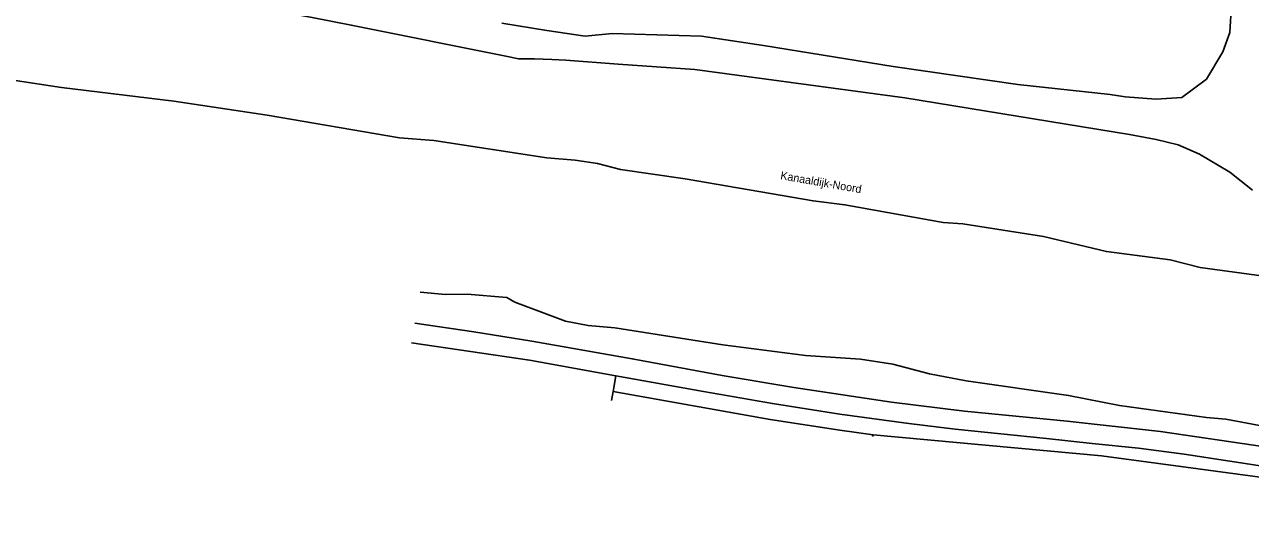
# Model space of a CAD drawing. Extents: x 164150 to 165261, y 382513 to 383432.
# Drawn here: x 165024.1 to 165177.4, y 382531.9 to 382595.7 of the extents above; entities that cross this region are included whole.
import ezdxf

# ---------------------------------------------------------------- set-up
doc = ezdxf.new("R2010")
doc.units = 0
for name, color, linetype in [('IMGEO_Berm_groen', 7, 'Continuous'), ('IMGEO_Fietspad_gesloten', 7, 'Continuous'), ('IMGEO_Hek', 7, 'Continuous'), ('IMGEO_Loofbos', 7, 'Continuous'), ('IMGEO_Openbare_ruimte_label', 7, 'Continuous'), ('IMGEO_Rijbaan_lokaal_onverhard', 7, 'Continuous'), ('IMGEO_Waterloop', 7, 'Continuous')]:
    doc.layers.add(name, color=color, linetype=linetype)

msp = doc.modelspace()

# ---------------------------------------------------------------- linework, layer by layer
at = {"layer": 'IMGEO_Berm_groen'}
for points in [[(165097.71, 382549.86), (165098.06, 382551.85)], [(165130.21, 382544.47), (165126.04, 382545.03), (165117.34, 382546.39), (165097.71, 382549.86)], [(165227.27, 382531.88), (165202.11, 382536.01), (165158.73, 382541.84), (165130.21, 382544.47)]]:
    msp.add_lwpolyline(points, dxfattribs=at)
at = {"layer": 'IMGEO_Fietspad_gesloten'}
for points in [[(165072.92, 382558.41), (165080.3, 382557.33), (165087.54, 382556.17), (165100.1, 382553.97), (165111.35, 382551.86), (165120.31, 382550.36), (165132.5, 382548.56), (165141.61, 382547.42), (165154.46, 382546.15), (165166.12, 382544.86), (165179.14, 382542.97), (165196.27, 382540.2), (165213.12, 382537.59), (165230.08, 382534.68)], [(165072.49, 382555.97), (165087.26, 382553.78), (165098.06, 382551.85)], [(165098.06, 382551.85), (165109.02, 382549.87), (165117.62, 382548.37), (165126.06, 382547.04), (165134.67, 382545.87), (165140.44, 382545.17), (165151.88, 382544), (165157.59, 382543.39), (165163.35, 382542.78), (165169.08, 382542.04), (165191.9, 382538.55), (165228.77, 382532.6)]]:
    msp.add_lwpolyline(points, dxfattribs=at)
at = {"layer": 'IMGEO_Hek'}
msp.add_lwpolyline([(165097.52, 382548.77), (165097.71, 382549.86)], dxfattribs=at)
at = {"layer": 'IMGEO_Loofbos'}
for points in [[(165097.71, 382549.86), (165097.52, 382548.77)], [(165130.21, 382544.47), (165130.13, 382544.27)]]:
    msp.add_lwpolyline(points, dxfattribs=at)
at = {"layer": 'IMGEO_Rijbaan_lokaal_onverhard'}
for points in [[(165022.71, 382602.49), (165025.2, 382602.49), (165028.36, 382602.25), (165044.09, 382599.56), (165060.08, 382596.6), (165064.98, 382595.66), (165084.72, 382591.68), (165085.9, 382591.44), (165087.86, 382591.43), (165090.05, 382591.38), (165091.81, 382591.26), (165098.35, 382590.8), (165107.91, 382590.12), (165134.15, 382586.57), (165162.23, 382582), (165165.56, 382581.35), (165168.32, 382580.68), (165170.98, 382579.55), (165174.78, 382577.3), (165177.6, 382575.04)], [(165175, 382598.25), (165174.79, 382594.74), (165173.9, 382592.34), (165171.86, 382588.92), (165168.77, 382586.62), (165165.59, 382586.41), (165161.71, 382586.69), (165159.83, 382587), (165148.27, 382588.24), (165132.69, 382590.47), (165116.52, 382593.1), (165108.74, 382594.28), (165097.57, 382594.62), (165094.22, 382594.3), (165089.43, 382595), (165083.81, 382595.92)]]:
    msp.add_lwpolyline(points, dxfattribs=at)
at = {"layer": 'IMGEO_Waterloop'}
for points in [[(165230.78, 382556.37), (165216.28, 382558.63), (165205.52, 382560.67), (165189.54, 382562.7), (165184.24, 382563.57), (165171.09, 382565.37), (165167.31, 382566.31), (165159.36, 382567.35), (165151.49, 382569.24), (165141.43, 382570.82), (165138.97, 382570.99), (165126.67, 382573.22), (165122.69, 382573.7), (165106.71, 382576.47), (165098.61, 382577.61), (165095.77, 382578.35), (165092.95, 382578.8), (165089.44, 382579.09), (165075.28, 382581.23), (165071.02, 382581.57), (165054.46, 382584.4), (165042.82, 382586.17), (165028.75, 382587.85), (165016.65, 382589.69)], [(165073.59, 382562.27), (165076.74, 382561.98), (165079.46, 382562.02), (165084.44, 382561.64), (165085.42, 382561.05), (165091.76, 382558.66), (165094.58, 382558.14), (165097.93, 382557.84), (165111.43, 382555.72), (165121.76, 382554.39), (165128.64, 382553.91), (165132.67, 382553.28), (165137.26, 382552.1), (165141.85, 382551.21), (165154.62, 382549.38), (165160.99, 382548.14), (165171.86, 382546.64), (165174.27, 382546.43), (165181.16, 382545.13)]]:
    msp.add_lwpolyline(points, dxfattribs=at)

# ---------------------------------------------------------------- texts
at = {"layer": 'IMGEO_Openbare_ruimte_label'}
msp.add_text('Kanaaldijk-Noord', height=1, rotation=350.0385, dxfattribs=at).set_placement((165118.56, 382576.42))

doc.saveas('drawing.dxf')
